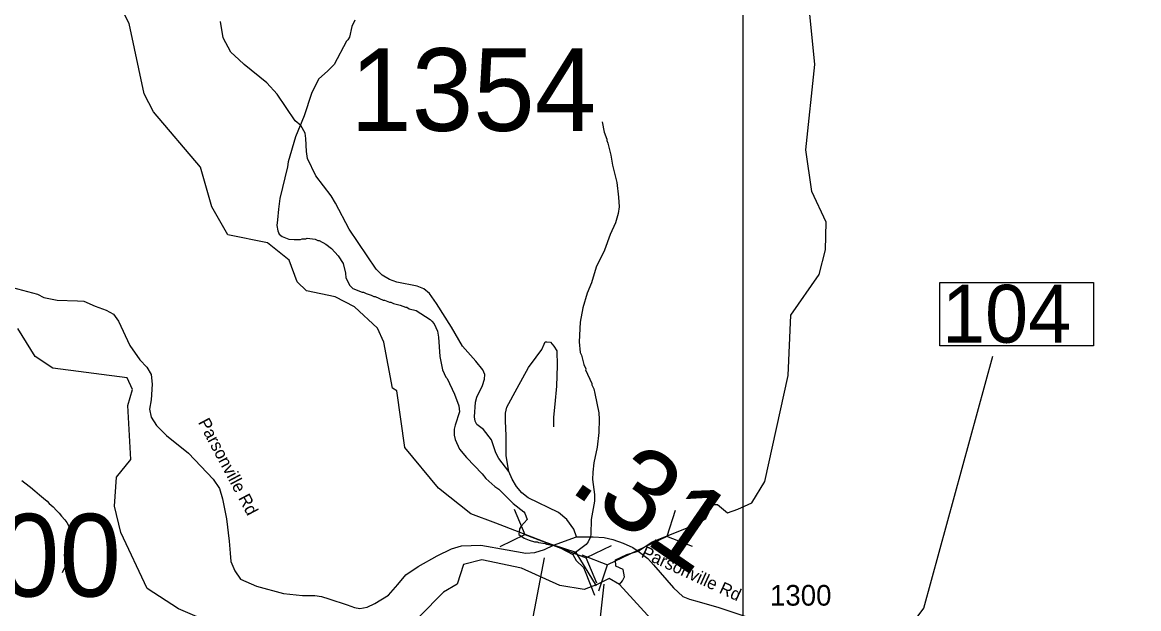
# Model space of a CAD drawing. Extents: x 1248089 to 1457196, y 820910 to 988753.
# Drawn here: x 1308669 to 1315416, y 901429 to 904975 of the extents above; entities that cross this region are included whole.
import ezdxf

# ---------------------------------------------------------------- set-up
doc = ezdxf.new("R2010")
doc.units = 0
for name, color, linetype in [('Exist Hydrographic Creek Single Shore', 7, 'Continuous'), ('Exist Hydrographic Misc Water Feature', 7, 'Continuous'), ('Exist Road Non-System Type 51', 7, 'Continuous'), ('Exist Road Secondary Structure Pipe CELL', 7, 'Continuous'), ('Exist Road Secondary Structure Standard Bridge Number Label', 7, 'Continuous'), ('Exist Road Secondary Type 41 Attributed', 7, 'Continuous'), ('Exist Road Secondary Type 51 Attributed', 7, 'Continuous'), ('Exist Road Secondary Type 51 Label', 7, 'Continuous'), ('Map Preparation Inset Cut Line', 7, 'Continuous'), ('Prop GRAU CAT1 Cell', 7, 'Continuous'), ('Prop Lane Arrow CELL', 7, 'Continuous'), ('Prop Lane Lines', 7, 'Continuous')]:
    doc.layers.add(name, color=color, linetype=linetype)

msp = doc.modelspace()

# ---------------------------------------------------------------- linework, layer by layer
at = {"layer": 'Exist Hydrographic Creek Single Shore'}
for points in [[(1311878.3, 901812.7), (1311839.8, 901827.7), (1311531.3, 901944.9), (1311380.4, 902001.6), (1311184.4, 902156.5), (1310981.4, 902403.5), (1310931.3, 902745.9), (1310906.4, 902762.9), (1310854.3, 903039.7), (1310814.4, 903125.8), (1310676.4, 903253.3), (1310560.4, 903314.8), (1310386.3, 903351), (1310329.3, 903404.8), (1310282.4, 903536.9), (1310151.3, 903641.4), (1309910.4, 903688.9), (1309814.3, 903858.2), (1309745.3, 904099.3), (1309461.3, 904433.3), (1309405.3, 904542.7), (1309315.3, 904968.1), (1309235.3, 905120.6)], [(1311334.2, 901696.2), (1311296.7, 901576.2), (1311214.8, 901528.3), (1310779.9, 901087.3), (1310709.1, 901066.4), (1310560, 901086.9), (1310450.7, 901207.7), (1310370.2, 901265.3), (1310191.8, 901276.4), (1309768.7, 901360.4), (1309612, 901427.1), (1309422.7, 901551.2), (1309263.8, 901889.2), (1309225.8, 902047.6), (1309237.8, 902224.6), (1309323.8, 902331.2), (1309306.8, 902656.5), (1309333.7, 902754.4), (1309301.7, 902824), (1308852.8, 902882.4), (1308746.8, 902953.4), (1308641.7, 903122.9)], [(1312278.1, 901574.1), (1312296.6, 901597.7), (1312308.1, 901622), (1312300.9, 901664.9), (1312256.6, 901686.3), (1312253.8, 901724.9), (1312322.3, 901756.4), (1312391.2, 901776.8), (1312475.2, 901833.5), (1312743.3, 901940.3)], [(1312139.7, 901567.5), (1312016.9, 901767.6), (1311878.3, 901812.7)], [(1312278.1, 901574.1), (1312215.2, 901611.3), (1312142.4, 901574.7), (1312063.8, 901545.5), (1311918.1, 901568.4), (1311685.5, 901673.3), (1311445.6, 901724.7), (1311334.2, 901696.2)], [(1313260.8, 900404.9), (1313086.5, 900469.9), (1313043.7, 900617.2), (1312932.2, 900798.7), (1312702.8, 900950.3), (1312606.9, 901119.6), (1312532.3, 901296.8), (1312278.1, 901574.1)]]:
    msp.add_lwpolyline(points, dxfattribs=at)
at = {"layer": 'Exist Hydrographic Misc Water Feature'}
for points in [[(1312743.3, 901940.3), (1312799.4, 901973.6), (1312839.4, 902059.4), (1312870.8, 902059.4), (1312930.8, 902007.9), (1312993.7, 902030.8), (1313078.8, 902068.7), (1313156.8, 902198.5), (1313296.9, 902839.1), (1313313.8, 903203.2), (1313485.8, 903449.2), (1313522.8, 903599.5), (1313526.8, 903766.9), (1313439.8, 903952.4), (1313403.8, 904202.7), (1313457.8, 904720.2), (1313415.6, 905146.3)], [(1310678.5, 904987.7), (1310659.3, 904948.4), (1310645.5, 904884.8), (1310637, 904869), (1310628.8, 904861.2), (1310552.9, 904719.5), (1310515.8, 904680.6), (1310458.2, 904630.2), (1310415.8, 904543.5), (1310372, 904408.8), (1310320.4, 904282.4), (1310276.1, 904131.6), (1310271.2, 904099.9), (1310225.9, 903909.2), (1310216.1, 903845.5), (1310210.8, 903780.6)], [(1312173.8, 904372.8), (1312186, 904310.5), (1312200.9, 904268), (1312200.7, 904260), (1312208.1, 904243.8), (1312226.1, 904171.3), (1312236.4, 904111), (1312261.6, 904006.4), (1312273, 903918), (1312275.4, 903858), (1312270.3, 903818.1), (1312254.7, 903762.6), (1312220.7, 903691.6), (1312188, 903596.6), (1312137.1, 903494), (1312108.4, 903398.9), (1312082.6, 903335.7), (1312056.1, 903248.5), (1312039.7, 903161), (1312034.4, 903043.2), (1312040.5, 902977), (1312048, 902960.8), (1312062.5, 902904.4), (1312073.7, 902880.1), (1312073.5, 902872.1), (1312111.3, 902791), (1312111.1, 902783), (1312122.4, 902758.7), (1312129.6, 902730.5), (1312152.4, 902614), (1312155.2, 902573.9), (1312153, 902493.9), (1312142.5, 902406.2), (1312123.8, 902310.8), (1312116.2, 902255), (1312115, 902209.1), (1312126.4, 902118.8), (1312127.3, 902078.8), (1312106.1, 901967.4), (1312105.6, 901879.5), (1312103.3, 901863.6), (1312088.3, 901832), (1312075.9, 901816.4), (1311995.2, 901755.6)], [(1310210.8, 903780.6), (1310207.3, 903745.7), (1310212.4, 903713.6), (1310221.8, 903693.3), (1310239.4, 903678.9), (1310279, 903663.7), (1310310.9, 903660.8), (1310351, 903661.7), (1310359.1, 903665.5), (1310383.1, 903664.7), (1310391.2, 903668.5), (1310439.1, 903663.1), (1310454.9, 903654.7), (1310462.8, 903654.4), (1310502.2, 903633.3), (1310537.5, 903606.3), (1310578.3, 903563.1), (1310607, 903516.3), (1310621.4, 903457.8), (1310624.6, 903429.9), (1310647.3, 903383.2), (1310666.8, 903364.7), (1310722.2, 903343), (1310730.2, 903342.8), (1310745.9, 903334.3), (1310777.7, 903325.4), (1310793.5, 903317), (1310801.5, 903316.8), (1310849, 903295.3), (1310857, 903295.1), (1310888.5, 903282.2), (1310896.5, 903282), (1310912.3, 903273.5), (1310952.1, 903264.4), (1310983.8, 903251.5), (1310991.8, 903251.3), (1311007.5, 903242.8), (1311049.2, 903231.6), (1311133.7, 903177.1), (1311143.4, 903166.9), (1311156.9, 903150.5), (1311177.8, 903105.9), (1311184.7, 903069.7), (1311191.5, 902953.6), (1311209.2, 902873), (1311228, 902828.5), (1311235.7, 902820.3), (1311281.1, 902725.1), (1311307, 902654.4), (1311310.1, 902618.3), (1311283.9, 902539), (1311279.2, 902515.2), (1311278.1, 902477.2), (1311285.4, 902451), (1311311.8, 902394.2), (1311352.4, 902343.1), (1311447.6, 902244.3), (1311470.9, 902215.7), (1311525.5, 902168.2), (1311549.1, 902151.5), (1311634.7, 902065), (1311699.3, 902015.2), (1311705.1, 902007), (1311720.6, 901968.5), (1311682.8, 901927.6), (1311674.4, 901912), (1311668.8, 901876.9), (1311702.8, 901855.2), (1311732.4, 901842.2), (1311764.2, 901833.3), (1311780.2, 901832.9), (1311788.1, 901828.7), (1311828, 901823.5), (1311835.9, 901819.3), (1311881.6, 901809.9), (1311919.2, 901796.9), (1311995.2, 901755.6)], [(1311995.2, 901755.6), (1312017.1, 901720.1), (1312060, 901676.9), (1312071.3, 901652.6), (1312126.1, 901510.3)]]:
    msp.add_lwpolyline(points, dxfattribs=at)
at = {"layer": 'Exist Road Non-System Type 51'}
for points in [[(1311608.8, 902257.4), (1311592.2, 902353.9), (1311592.2, 902475.2), (1311588.3, 902561.8), (1311588.3, 902611.9), (1311598, 902646.6), (1311659.5, 902762.1), (1311728.8, 902887.2), (1311775, 902948.9), (1311807.7, 902997), (1311823.1, 903027.8), (1311828.9, 903043.2), (1311838.5, 903043.2), (1311861.6, 903039.4), (1311880.8, 903016.3), (1311900.1, 902987.4), (1311902, 902898.8), (1311898.1, 902773.6), (1311886.6, 902665.8), (1311878.9, 902586.9), (1311878.9, 902529.1)], [(1308666.4, 902204.3), (1308683.9, 902189.9), (1308717.4, 902163.2), (1308745, 902140.4), (1308772.3, 902117.9), (1308795.9, 902097.2), (1308819.6, 902078.7), (1308831.1, 902064.5), (1308854.7, 902043.8), (1308874.3, 902023.4), (1308892, 902007), (1308905.4, 901988.7), (1308925, 901966.1), (1308936.7, 901949.9), (1308950, 901927.6), (1308959.6, 901905.4), (1308971.1, 901882.9), (1308974.5, 901858.9), (1308973.8, 901824.9), (1308967, 901797), (1308960.4, 901765.3), (1308949.6, 901735.5), (1308932.5, 901691.8), (1308909.6, 901646.2)]]:
    msp.add_lwpolyline(points, dxfattribs=at)
at = {"layer": 'Exist Road Secondary Structure Pipe CELL'}
for p, q in [((1311642.2, 902030.8), (1311706.2, 901877)), ((1312615.1, 902022.8), (1312563.5, 901864.4)), ((1311556.1, 901804.8), (1311706.2, 901877)), ((1311706.2, 901877), (1312077, 901735.8)), ((1312563.5, 901864.4), (1312205.1, 901694.2)), ((1312718.8, 901804.3), (1312563.5, 901864.4)), ((1312227, 901808), (1312077, 901735.8)), ((1312049.8, 901754.3), (1312205.1, 901694.2)), ((1312140.9, 901582), (1312077, 901735.8)), ((1312153.5, 901535.8), (1312205.1, 901694.2))]:
    msp.add_line(p, q, dxfattribs=at)
at = {"layer": 'Exist Road Secondary Structure Standard Bridge Number Label'}
msp.add_lwpolyline([(1314214.9, 903401.4), (1315143.9, 903401.4), (1315143.9, 903017.3), (1314214.9, 903017.3)], close=True, dxfattribs=at)
msp.add_lwpolyline([(1313373.2, 900433.7), (1314117, 901431.5), (1314534.3, 902955.4)], dxfattribs=at)
at = {"layer": 'Exist Road Secondary Type 41 Attributed'}
msp.add_lwpolyline([(1312017.6, 901862.2), (1312002.4, 901909.5), (1311959.6, 901967.6), (1311909.6, 902011.3), (1311726.4, 902098.4), (1311688.2, 902129), (1311656.1, 902167.2), (1311630.2, 902211.5), (1311608.8, 902257.4), (1311549.2, 902336.8), (1311530.9, 902370.4), (1311504.9, 902449.9), (1311456.1, 902511.4), (1311414.9, 902542), (1311405.7, 902561.9), (1311401.2, 902589.4), (1311407.3, 902678), (1311416.4, 902708.6), (1311450, 902778.9), (1311462.2, 902817.1), (1311463.8, 902844.6), (1311451.5, 902872.1), (1311410.4, 902924.8), (1311329.4, 903016.5), (1311262.2, 903131.1), (1311172.1, 903274.8), (1311129.4, 903334.4), (1311095.8, 903361.9), (1311055.4, 903379.3), (1310931.7, 903402.3), (1310887.4, 903419.1), (1310843.1, 903445.1), (1310808, 903481.7), (1310644.6, 903723.2), (1310562.1, 903880.6), (1310534.7, 903925.7), (1310443.1, 904046.4), (1310392.7, 904150.4), (1310386.5, 904193.2), (1310382, 904271.1), (1310378.9, 904304.7), (1310353, 904350.6), (1310317, 904378.7), (1310208.6, 904539.2), (1310146, 904609.5), (1310010, 904719.5), (1309978, 904750.1), (1309928.1, 904794), (1309882.3, 904879.8), (1309866.6, 904979.9)], dxfattribs=at)
at = {"layer": 'Exist Road Secondary Type 51 Attributed'}
for points in [[(1308579.5, 903379.1), (1308760.2, 903330.2), (1308799.1, 903310.8), (1308878.4, 903294.6), (1309001.4, 903291.3), (1309040.3, 903288.1), (1309108.3, 903258.9), (1309174.6, 903233), (1309219.9, 903208.7), (1309250.7, 903166.6), (1309318.7, 903020.8), (1309379.7, 902932.6), (1309421.8, 902888.8), (1309447.7, 902845.1), (1309452.6, 902786.8), (1309447.7, 902691.2), (1309438, 902634.5), (1309447.7, 902585.9), (1309480.1, 902537.3), (1309540, 902475.7), (1309672.2, 902370), (1309821.2, 902211.2), (1309860, 902156.2), (1309879.5, 902093), (1309903.7, 901971.5), (1309918.3, 901837), (1309924.7, 901763.6), (1309928, 901713.4), (1309953.9, 901656.7), (1309987.9, 901608.1), (1310083.4, 901564.4), (1310246.9, 901520.6), (1310361.8, 901507.7), (1310436.3, 901507.7), (1310477.6, 901503.1), (1310521.3, 901488.5), (1310631.4, 901451.2), (1310676.7, 901435), (1310709.1, 901430.2), (1310752.8, 901438.3), (1310799.7, 901461), (1310882.3, 901511.2), (1310939, 901574.4), (1310985.9, 901634.3), (1311060.4, 901684.5), (1311176.1, 901748.6), (1311263.5, 901790.8), (1311323.4, 901808.6), (1311440, 901813.4), (1311599.8, 901785.5), (1311711.2, 901764.1), (1311766.9, 901768.3), (1311824.1, 901786.9), (1311878.3, 901812.7), (1312017.6, 901862.2)], [(1312017.6, 901862.2), (1312119.5, 901863.6), (1312185.2, 901859.3), (1312238.1, 901846.4), (1312299.5, 901825), (1312358.1, 901797.8), (1312391.2, 901776.8), (1312449.5, 901733.1), (1312483.4, 901694.2), (1312604.9, 901554.9), (1312661.5, 901503), (1312700.4, 901485.2), (1312760.3, 901470.6), (1312878.4, 901436.6), (1313029.8, 901385.5), (1313259.6, 901312.6), (1313428, 901254.3), (1313500.3, 901222.8)]]:
    msp.add_lwpolyline(points, dxfattribs=at)
at = {"layer": 'Map Preparation Inset Cut Line'}
msp.add_lwpolyline([(1313026.2, 913085.2), (1388709.5, 913085.2), (1388709.5, 884379.9), (1373500.6, 884376.6), (1373500.6, 868836.7), (1313026.2, 868836.7)], close=True, dxfattribs=at)
at = {"layer": 'Prop Lane Arrow CELL'}
for points in [[(1311823.1, 901736.6), (1311592.8, 900533.7), (1311336.8, 900047.4)], [(1312182.9, 901576.6), (1312112.2, 900940.5), (1312027.9, 895952.3)]]:
    msp.add_lwpolyline(points, dxfattribs=at)

# ---------------------------------------------------------------- texts
at = {"layer": 'Exist Road Secondary Structure Standard Bridge Number Label'}
msp.add_text('104', height=350, dxfattribs=at).set_placement((1314227.5, 903037.1))
at = {"layer": 'Exist Road Secondary Type 51 Label'}
for rotation, p in [(297.89413, (1309728.9, 902556.2)), (335.29601, (1312403.9, 901742.8))]:
    msp.add_text('Parsonville Rd', height=75, rotation=rotation, dxfattribs=at).set_placement(p)
at = {"layer": 'Prop GRAU CAT1 Cell'}
msp.add_text('.31', height=500, rotation=325.46356, dxfattribs=at).set_placement((1311962.2, 902148.6))
at = {"layer": 'Prop Lane Lines'}
for s, height, p in [('1354', 500, (1310650.2, 904317.9)), ('1300', 500, (1307777.7, 901502.1)), ('1300', 125, (1313187.5, 901447.1))]:
    msp.add_text(s, height=height, dxfattribs=at).set_placement(p)

doc.saveas('drawing.dxf')
